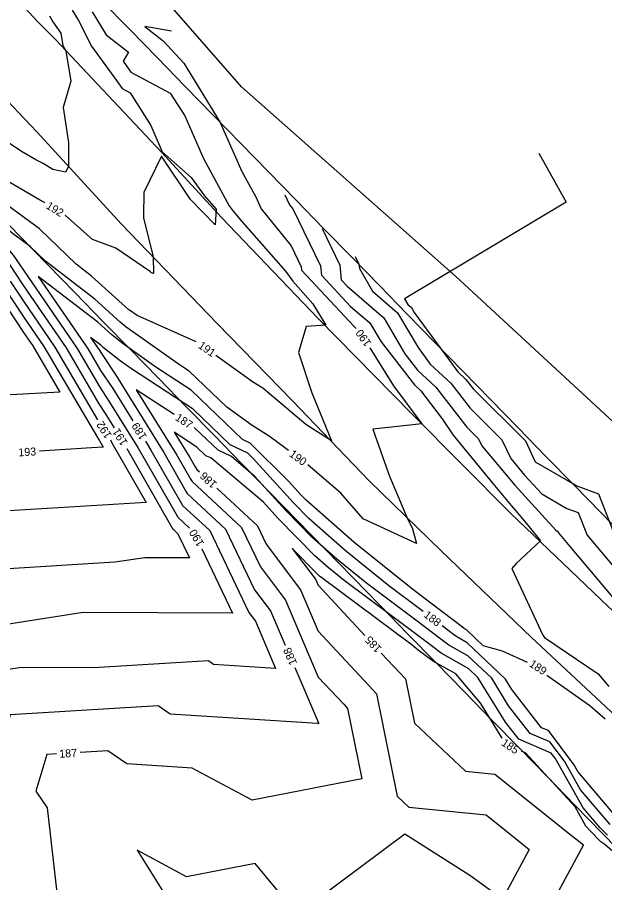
# Model space of a CAD drawing. Extents: x 2086416 to 2115205, y 575507 to 632762.
# Drawn here: x 2110278.4 to 2110425.2, y 581864.8 to 582081.1 of the extents above; entities that cross this region are included whole.
import ezdxf

# ---------------------------------------------------------------- set-up
doc = ezdxf.new("R2010")
doc.units = 0
for name, color, linetype in [('DTM Contours Major', 7, 'Continuous'), ('DTM Contours Major Text', 7, 'Continuous'), ('DTM Contours Minor', 7, 'Continuous'), ('DTM Contours Minor Text', 7, 'Continuous'), ('Exist Hydrographic FEMA Cross Section', 7, 'Continuous'), ('Exist Roads EOP', 7, 'Continuous'), ('Exist Vegetation Woods Line', 7, 'Continuous')]:
    doc.layers.add(name, color=color, linetype=linetype)

msp = doc.modelspace()

# ---------------------------------------------------------------- linework, layer by layer
at = {"layer": 'DTM Contours Major'}
for points in [[(2110316.89, 582077.63), (2110310.21, 582078.77), (2110314.85, 582075.2), (2110320.04, 582069.66), (2110329.12, 582054.79), (2110334.54, 582042.53), (2110337.96, 582036.21), (2110339.37, 582033.23), (2110346.83, 582023.95), (2110349.35, 582018.71), (2110349.43, 582017.88), (2110362.56, 582003.85), (2110363.03, 582003.44), (2110363.07, 582003.38)], [(2110265.4, 582035.83), (2110277.36, 582021.68), (2110279.01, 582019.19), (2110279.89, 582017.86), (2110293.32, 581998.29), (2110298.98, 581988.65), (2110301.29, 581985.18), (2110308.53, 581973.54), (2110318.39, 581956.29), (2110318.49, 581956.12), (2110321.45, 581953.37)], [(2110346.2, 581972.79), (2110341.33, 581976.42), (2110337.08, 581979.04), (2110330.74, 581983.65), (2110321.37, 581992.65), (2110319.17, 581994.09), (2110305.61, 582003.68), (2110304.12, 582004.86), (2110297.71, 582010.63), (2110285.4, 582020.11), (2110281.57, 582023.82), (2110277.77, 582026.61), (2110267.71, 582034.46)], [(2110366.53, 581998.49), (2110372.41, 581988.98), (2110379.53, 581979.5), (2110372.67, 581978.77), (2110367.29, 581978.19), (2110371.09, 581967.34), (2110371.56, 581965.98), (2110375.71, 581956.12), (2110377.13, 581953.24), (2110378.15, 581949.58), (2110364.85, 581955.76), (2110359.29, 581962.12), (2110351.01, 581969.2)], [(2110324.46, 581948.27), (2110332.16, 581932.18), (2110294.81, 581932.29), (2110269.72, 581928.4), (2110263.82, 581928.04), (2110261.87, 581927.92), (2110261.42, 581927.97), (2110260.59, 581928.07), (2110255.91, 581922.27), (2110255.52, 581921), (2110255.06, 581919.59)], [(2110399.57, 581900.92), (2110394.25, 581909.56), (2110387.99, 581916.96), (2110382.41, 581920.1), (2110378.62, 581922.94), (2110377.05, 581924.14), (2110354.52, 581940.97), (2110353.93, 581941.45), (2110353.44, 581941.88), (2110347.12, 581948.36), (2110352.92, 581940.64), (2110353.57, 581939.12), (2110365.28, 581926.58)], [(2110369.37, 581922.2), (2110372.5, 581918.84), (2110375.41, 581915.72), (2110377.65, 581904.64), (2110390.4, 581892.7), (2110397.79, 581891.94), (2110416.83, 581876.68), (2110419.88, 581874.24), (2110407.25, 581850.79)], [(2110477.66, 581830.47), (2110467.52, 581837.44), (2110466.26, 581838.39), (2110465.28, 581839.19), (2110446.86, 581855.82), (2110445.45, 581856.9), (2110444.68, 581857.31), (2110425.22, 581874.31), (2110424.26, 581875.03), (2110421.59, 581877.72), (2110420.54, 581878.96), (2110417.81, 581883.75), (2110405.43, 581897.24), (2110404.4, 581897.68)]]:
    msp.add_lwpolyline(points, dxfattribs=at)
at = {"layer": 'DTM Contours Minor'}
for points in [[(2110239.63, 582076.69), (2110234.85, 582080.48), (2110227.63, 582086.48), (2110212.34, 582095.86), (2110223.97, 582080.06), (2110225.38, 582078.5), (2110237.38, 582062.8), (2110241.12, 582057.39), (2110253.02, 582043.75), (2110256.71, 582037.96), (2110256.86, 582037.78), (2110266.82, 582025.99), (2110275.38, 582013.07), (2110279.92, 582006.23), (2110285.03, 581998.78), (2110298.39, 581976.04), (2110298.49, 581975.89), (2110298.8, 581975.39), (2110299.81, 581973.62), (2110296.89, 581973.45), (2110283.89, 581972.66)], [(2110292.08, 582082.87), (2110293.64, 582080.28), (2110296.88, 582073.9), (2110303.18, 582065.27), (2110304.59, 582063.3), (2110306.62, 582062.23), (2110311.76, 582054.07), (2110314.61, 582047.48), (2110321.83, 582041.03), (2110325.2, 582036.5), (2110328.05, 582033.12), (2110327.81, 582029.25), (2110321.69, 582035.56), (2110314.41, 582046.42), (2110309.98, 582037.35), (2110309.94, 582031.5), (2110309.89, 582030.94), (2110312.31, 582021.21), (2110312.43, 582017.13), (2110312.3, 582017.07), (2110311.76, 582017.34), (2110311.65, 582017.5), (2110303.02, 582023.39), (2110297.14, 582025.56), (2110290.52, 582031.45), (2110290.36, 582031.55)], [(2110297.06, 582082.5), (2110300.58, 582076.68), (2110306.18, 582072.38), (2110304.81, 582070.11), (2110306.76, 582067.39), (2110316.62, 582062.17), (2110320.22, 582056.47), (2110324.91, 582045.84), (2110331.33, 582033.98), (2110332.3, 582032.66), (2110334.52, 582030.03), (2110345.38, 582017.66), (2110347.26, 582015.14), (2110352.23, 582009.51), (2110355.48, 582004.16), (2110350.59, 582003.84), (2110348.66, 581997.34), (2110351.99, 581987.24), (2110356.93, 581975.27), (2110350.5, 581979.3), (2110339.72, 581988.41), (2110337.16, 581989.99), (2110335.08, 581991.5), (2110327.98, 581996.6)], [(2110286.44, 582081.48), (2110287.22, 582079.93), (2110289.28, 582077.11), (2110289.71, 582074.07), (2110290.54, 582072.75), (2110291.77, 582065.16), (2110289.82, 582058.59), (2110291.13, 582049.84), (2110291.2, 582043.81), (2110290.42, 582042.42), (2110287.21, 582043.02), (2110284.81, 582044.52), (2110282.98, 582045.45), (2110279.43, 582047.55), (2110274.33, 582051.01), (2110267.62, 582055.41), (2110261.78, 582062.06), (2110255.13, 582066.52), (2110245.2, 582072.27), (2110244.33, 582072.96)], [(2110323.07, 582000.02), (2110308.3, 582006.54), (2110306.38, 582007.9), (2110306.25, 582008), (2110296.94, 582016.39), (2110293.07, 582019.36), (2110283.91, 582028.25), (2110274.82, 582034.9), (2110263.82, 582043.5), (2110263.61, 582043.67), (2110259.77, 582048.03), (2110243.43, 582058.99), (2110257.37, 582043), (2110258.38, 582041.42), (2110258.61, 582041.15), (2110273.85, 582023.12), (2110277.8, 582017.15), (2110279.9, 582013.99), (2110290.56, 581998.46), (2110298.79, 581984.45), (2110300.36, 581982.08), (2110302.61, 581978.47)], [(2110408.74, 582047.16), (2110415.62, 582034.86), (2110375.19, 582010.71), (2110376.01, 582009.3), (2110376.89, 582008.54), (2110377.61, 582007.32), (2110388.47, 581992.46), (2110390.48, 581990.58), (2110392.38, 581988.12), (2110405.41, 581975.28), (2110407.87, 581969.97), (2110410, 581968.7), (2110418.21, 581964.01), (2110423.65, 581961.96), (2110428, 581950.92)], [(2110285.28, 582034.73), (2110285.17, 582034.79), (2110283.74, 582035.52), (2110276.51, 582039.81)], [(2110255.45, 582036.89), (2110255.87, 582036.23), (2110255.98, 582036.1), (2110263.31, 582027.43), (2110274.17, 582011.04), (2110279.93, 582002.35), (2110282.27, 581998.95), (2110289.03, 581987.44), (2110276.79, 581986.7), (2110269.64, 581987.54), (2110256.43, 581989.07), (2110188.99, 581905.51)], [(2110345.27, 582036.72), (2110346.44, 582034.26), (2110347.29, 582033.2), (2110354.16, 582018.94), (2110354.38, 582016.68), (2110361.69, 582008.85), (2110366.5, 582004.71), (2110369.3, 581999.97), (2110377.63, 581989.21), (2110379.25, 581987.7), (2110384.62, 581980.75), (2110387.34, 581976.65), (2110397.29, 581964.54), (2110401.81, 581959.08), (2110402.88, 581957.8), (2110405.13, 581955.2), (2110409.18, 581950.28), (2110403.07, 581944.54), (2110402.04, 581943.3), (2110409.75, 581926.69), (2110410.17, 581926.05), (2110423.62, 581917), (2110426.24, 581913.8)], [(2110354.56, 582028.31), (2110358.97, 582019.17), (2110359.33, 582015.47), (2110360.83, 582013.86), (2110369.96, 582005.99), (2110375.29, 581996.97), (2110378.43, 581992.92), (2110382.99, 581988.66), (2110390.74, 581978.63), (2110393.67, 581975.74), (2110394.48, 581974), (2110402.75, 581964.19), (2110412.98, 581952.89), (2110413.32, 581952.69), (2110413.47, 581952.63), (2110413.6, 581952.32), (2110416.54, 581948.84), (2110428.57, 581934.53)], [(2110362.85, 582021.33), (2110363.78, 582019.4), (2110363.88, 582018.32), (2110367.16, 582012.67), (2110373.42, 582007.27), (2110378.55, 581998.6), (2110381.62, 581994.4), (2110386.74, 581989.62), (2110391.56, 581983.38), (2110399.54, 581975.51), (2110401.73, 581970.79), (2110405.19, 581966.68), (2110409.47, 581961.95), (2110415.77, 581958.35), (2110418.56, 581957.29), (2110420.8, 581951.62), (2110431.76, 581938.65)], [(2110405.88, 581919.83), (2110399.66, 581922.63), (2110394.85, 581924.01), (2110390.64, 581928.01), (2110390.16, 581928.28), (2110389.96, 581928.43), (2110379, 581936.77), (2110376.85, 581938.38), (2110362.49, 581949.91), (2110350.59, 581960.4), (2110349.35, 581961.67), (2110346.16, 581965.18), (2110336.6, 581974.67), (2110334.68, 581975.56), (2110321.84, 581987.9), (2110313.03, 581993.67), (2110304.83, 581999.47), (2110301.99, 582001.72), (2110298.49, 582004.88), (2110283.58, 582016.35), (2110296.08, 581998.13), (2110299.18, 581992.85), (2110302.22, 581988.28), (2110307.23, 581980.22)], [(2110276.59, 582015.11), (2110279.91, 582010.11), (2110287.79, 581998.62), (2110298.43, 581980.52)], [(2110379.82, 581932.62), (2110378.51, 581933.61), (2110371.27, 581939.03), (2110360.35, 581947.8), (2110351.3, 581955.77), (2110347.4, 581959.76), (2110337.34, 581970.85), (2110335.99, 581972.19), (2110331.62, 581974.22), (2110322.31, 581983.16), (2110306.9, 581993.24), (2110304.06, 581995.25), (2110299.86, 581998.58), (2110299.26, 581999.13), (2110296.69, 582001.1), (2110298.84, 581997.97), (2110299.38, 581997.06), (2110303.15, 581991.38), (2110315.02, 581972.3), (2110320.62, 581962.5), (2110320.86, 581962.1), (2110330.44, 581953.2), (2110337.7, 581938.02), (2110341.66, 581932.76), (2110345.35, 581924.13)], [(2110317.59, 581981.81), (2110308.1, 581988.02), (2110318.26, 581971.68), (2110321.73, 581965.61), (2110322.05, 581965.09), (2110334.43, 581953.59), (2110339.15, 581943.72), (2110345.42, 581935.38), (2110353.62, 581916.19), (2110359.97, 581909.4), (2110360.94, 581908.35), (2110364.51, 581890.73), (2110337.12, 581885.39), (2110322.05, 581893.45), (2110305.74, 581894.49), (2110300.99, 581897.73), (2110294.12, 581897.32)], [(2110426.61, 581879.3), (2110419.19, 581888.04), (2110415.15, 581895.13), (2110411.53, 581899.97), (2110406.61, 581902.08), (2110401.2, 581909.01), (2110396.96, 581915.88), (2110391.03, 581921.51), (2110386.29, 581924.19), (2110384.29, 581925.69), (2110378.03, 581930.45), (2110365.69, 581939.68), (2110358.21, 581945.68), (2110352.01, 581951.14), (2110345.46, 581957.85), (2110337.74, 581966.36), (2110331.96, 581971.23), (2110331.71, 581971.4), (2110328.55, 581972.87), (2110322.79, 581978.41), (2110322.61, 581978.53)], [(2110425.95, 581876.64), (2110424.1, 581878.51), (2110419.86, 581883.5), (2110412.81, 581895.89), (2110411.87, 581897.15), (2110403.76, 581900.63), (2110400.42, 581904.91), (2110393.53, 581916.08), (2110391.23, 581918.26), (2110384.35, 581922.15), (2110381.46, 581924.31), (2110377.54, 581927.29), (2110360.1, 581940.32), (2110356.07, 581943.56), (2110352.73, 581946.51), (2110343.51, 581955.95), (2110339.94, 581959.88), (2110327.26, 581970.57), (2110326.71, 581970.96), (2110325.49, 581971.52), (2110323.26, 581973.67), (2110317.58, 581977.38), (2110321.51, 581971.06), (2110322.85, 581968.71), (2110323.24, 581968.08), (2110323.9, 581967.47)], [(2110301.63, 581975.45), (2110302.04, 581974.77), (2110310.59, 581959.81), (2110285.87, 581958.31), (2110269.33, 581957.31), (2110265.53, 581957.76), (2110258.51, 581958.57), (2110218.92, 581909.52), (2110215.63, 581898.75), (2110210.19, 581881.92), (2110223.48, 581854.62), (2110225.48, 581847.63), (2110225.52, 581847.51)], [(2110310.4, 581975.13), (2110311.78, 581972.92), (2110319.5, 581959.4), (2110319.67, 581959.11), (2110326.46, 581952.81), (2110336.26, 581932.33), (2110337.91, 581930.13), (2110342.94, 581918.36), (2110327.45, 581919.35), (2110326.2, 581920.21), (2110297.45, 581918.49), (2110279.39, 581918.55), (2110267.52, 581916.71), (2110261.26, 581895.57), (2110257.09, 581881.5), (2110257.62, 581880.73), (2110258.31, 581874.72), (2110261.9, 581860.82)], [(2110305.75, 581973.35), (2110317.27, 581953.18), (2110317.3, 581953.14), (2110318.49, 581952.03), (2110321.38, 581945.99), (2110310.24, 581946.03), (2110302.75, 581944.87), (2110274.84, 581943.18), (2110265.6, 581942.62), (2110263.47, 581942.87), (2110259.55, 581943.32), (2110237.41, 581915.9), (2110235.58, 581909.87), (2110226.31, 581881.2), (2110234.36, 581864.64), (2110238.85, 581848.99)], [(2110328.29, 581963.38), (2110338.41, 581953.97), (2110340.59, 581949.41), (2110349.17, 581938.01), (2110353.6, 581927.66), (2110366.24, 581914.12), (2110368.17, 581912.04), (2110373.36, 581886.45), (2110376.29, 581883.71), (2110395.58, 581881.74), (2110404.88, 581874.28), (2110406.37, 581873.09), (2110399.68, 581860.65), (2110391.46, 581866.63), (2110375.29, 581876.92), (2110353.26, 581860.55)], [(2110429.12, 581880.09), (2110418.51, 581892.57), (2110417.49, 581894.37), (2110411.18, 581902.8), (2110409.45, 581903.54), (2110401.98, 581913.11), (2110400.39, 581915.69), (2110390.83, 581924.76), (2110388.22, 581926.24), (2110387.12, 581927.06), (2110384.59, 581928.99)], [(2110347.71, 581918.62), (2110353.65, 581904.72), (2110353.7, 581904.68), (2110353.7, 581904.67), (2110353.73, 581904.55), (2110353.54, 581904.51), (2110353.43, 581904.57), (2110316.59, 581906.92), (2110313.59, 581908.97), (2110276.62, 581906.77), (2110270.04, 581884.58), (2110271.75, 581882.11), (2110273.92, 581863.02), (2110279.51, 581841.39), (2110280.82, 581837.67), (2110289.39, 581831.97), (2110290.63, 581826.76), (2110299.16, 581809.22)], [(2110425.3, 581905.63), (2110421.47, 581908.98), (2110410.78, 581916.6)], [(2110288.13, 581896.97), (2110285.71, 581896.82), (2110283, 581887.65), (2110285.87, 581883.5), (2110289.54, 581851.33), (2110290.58, 581847.3), (2110290.82, 581846.6), (2110292.92, 581845.21), (2110300.94, 581850.81), (2110307.98, 581835.94), (2110308.72, 581829.44), (2110328.04, 581798.41), (2110328.28, 581797.91), (2110328.33, 581797.81), (2110328.36, 581797.69), (2110328.67, 581797.32), (2110340.79, 581768.09), (2110341.88, 581750.11), (2110347.64, 581742.54), (2110348.83, 581732.84), (2110349.85, 581729.37)], [(2110348.44, 581856.97), (2110348.37, 581856.91), (2110337.84, 581869.61), (2110320.7, 581866.27), (2110308.32, 581872.89), (2110315.01, 581862.24), (2110322.51, 581850.28), (2110327.68, 581839.37), (2110329.34, 581824.75), (2110333.87, 581817.46), (2110344.38, 581809.08), (2110345.17, 581808.24), (2110347.25, 581777.74), (2110352.06, 581766.14), (2110352.48, 581759.21), (2110359.23, 581750.34), (2110362.78, 581746.53), (2110364.99, 581737.98)]]:
    msp.add_lwpolyline(points, dxfattribs=at)
at = {"layer": 'Exist Hydrographic FEMA Cross Section'}
for points in [[(2110431.36, 581950.02), (2110424.42, 581957.13), (2110417.48, 581964.24), (2110410.54, 581971.35), (2110403.6, 581978.47), (2110396.67, 581985.58), (2110389.73, 581992.69), (2110382.79, 581999.81), (2110375.85, 582006.91), (2110368.91, 582014.03), (2110361.97, 582021.14), (2110355.03, 582028.25), (2110348.09, 582035.36), (2110341.16, 582042.48), (2110334.22, 582049.59), (2110327.28, 582056.7), (2110320.34, 582063.82), (2110313.4, 582070.93), (2110306.46, 582078.04), (2110299.52, 582085.15)], [(2110431.63, 581869.96), (2110424.69, 581877.07), (2110417.76, 581884.19), (2110410.82, 581891.3), (2110403.88, 581898.41), (2110396.94, 581905.52), (2110390, 581912.63), (2110383.06, 581919.75), (2110376.12, 581926.86), (2110369.18, 581933.97), (2110362.24, 581941.08), (2110355.3, 581948.2), (2110348.36, 581955.31), (2110341.43, 581962.42), (2110334.49, 581969.53), (2110327.55, 581976.64), (2110320.61, 581983.76), (2110313.67, 581990.87), (2110306.73, 581997.98), (2110299.79, 582005.09), (2110292.85, 582012.21), (2110285.92, 582019.32), (2110278.97, 582026.43), (2110272.04, 582033.54)]]:
    msp.add_lwpolyline(points, dxfattribs=at)
at = {"layer": 'Exist Roads EOP'}
for points in [[(2110283.42, 582080.08), (2110269.79, 582094.77), (2110258.57, 582106.89), (2110244.84, 582121.04), (2110232.61, 582133.97), (2110220.43, 582147.01), (2110205.56, 582162.74), (2110193.7, 582175.26), (2110182.38, 582187.32), (2110170.57, 582200.14), (2110157.55, 582213.9), (2110148.13, 582223.91), (2110139.67, 582233.18), (2110129.17, 582244.2), (2110118.25, 582256.11), (2110105.57, 582269.53), (2110093.37, 582282.59), (2110082.14, 582294.76), (2110071.88, 582305.53), (2110059.32, 582319.17)], [(2110044.03, 582306.54), (2110057.72, 582292.25), (2110067.42, 582282.08), (2110077.05, 582271.73), (2110082.67, 582265.54), (2110091.18, 582256.81), (2110101.9, 582244.92), (2110112.61, 582233.51), (2110124.83, 582220.15), (2110138.66, 582205.71), (2110150.44, 582192.87), (2110163.31, 582179.2), (2110176.51, 582165.18), (2110187.09, 582154.1), (2110200.16, 582140.29), (2110212.15, 582128.06), (2110221.2, 582117.92), (2110235.62, 582102.6), (2110247.94, 582089.65), (2110262.41, 582074.68), (2110272.71, 582063.48), (2110283.25, 582052.48)], [(2110680.73, 581755.98), (2110662.27, 581765.85), (2110648.84, 581772.92), (2110632.22, 581782.31), (2110614.63, 581792.7), (2110596.64, 581803.91), (2110578.53, 581815.64), (2110567.83, 581822.57), (2110553.15, 581832.42), (2110531.54, 581847.48), (2110510.05, 581863.33), (2110489.25, 581879.31), (2110463.15, 581900.73), (2110445.32, 581916.19), (2110426.12, 581933.84), (2110401.78, 581957.07), (2110377.09, 581981.9), (2110353.55, 582005.81), (2110329.43, 582031.08), (2110314.39, 582047.38), (2110299.73, 582063), (2110287.89, 582075.57), (2110283.42, 582080.08)], [(2110283.25, 582052.48), (2110304.42, 582029.37), (2110328.36, 582004.6), (2110347.1, 581985.36), (2110366.35, 581965.28), (2110384.3, 581947.72), (2110406.89, 581926.12), (2110426.78, 581907.62), (2110438.72, 581896.56), (2110454.4, 581883.19), (2110469.83, 581870.54), (2110488.57, 581855.49), (2110506.88, 581841.42), (2110523.82, 581828.96), (2110539, 581818.5), (2110552.64, 581809.38), (2110568.55, 581798.72), (2110587.98, 581786.4), (2110607.77, 581774.2), (2110633.24, 581759.62), (2110661.71, 581744.29), (2110681.63, 581733.96)]]:
    msp.add_lwpolyline(points, dxfattribs=at)
at = {"layer": 'Exist Vegetation Woods Line'}
msp.add_lwpolyline([(2111059.79, 581657.65), (2110968.73, 581672.25), (2110864.06, 581705.25), (2110784.73, 581740.8), (2110702.3, 581784.67), (2110632.54, 581823.34), (2110568.48, 581865.95), (2110498.27, 581913.79), (2110441.66, 581966.78), (2110387.94, 582016.39), (2110334.43, 582063.69), (2110284.48, 582120.87)], dxfattribs=at)

# ---------------------------------------------------------------- texts
at = {"layer": 'DTM Contours Major Text'}
for s, rotation, p in [('190', 125.2488, (2110366.99, 581999.69)), ('190', 323.2405, (2110346.18, 581971.56)), ('190', 120.5563, (2110325.18, 581949.53)), ('185', 133.029, (2110369.61, 581923.41)), ('185', 326.1225, (2110399.2, 581899.3))]:
    msp.add_text(s, height=2, rotation=rotation, dxfattribs=at).set_placement(p)
at = {"layer": 'DTM Contours Minor Text'}
for s, rotation, p in [('192', 327.997, (2110285.36, 582033.49)), ('191', 325.112, (2110323.38, 581998.63)), ('187', 326.81, (2110317.65, 581980.58)), ('192', 122.2396, (2110302.1, 581976.6)), ('189', 121.8893, (2110310.87, 581976.27)), ('191', 121.5585, (2110306.06, 581974.79)), ('193', 3.4666, (2110278.68, 581971.34)), ('186', 137.0916, (2110328.44, 581964.61)), ('188', 322.7289, (2110379.79, 581931.39)), ('188', 113.1517, (2110348.35, 581919.68)), ('189', 326.6507, (2110406.16, 581919.02)), ('187', 3.4125, (2110288.91, 581896.01))]:
    msp.add_text(s, height=2, rotation=rotation, dxfattribs=at).set_placement(p)

doc.saveas('drawing.dxf')
